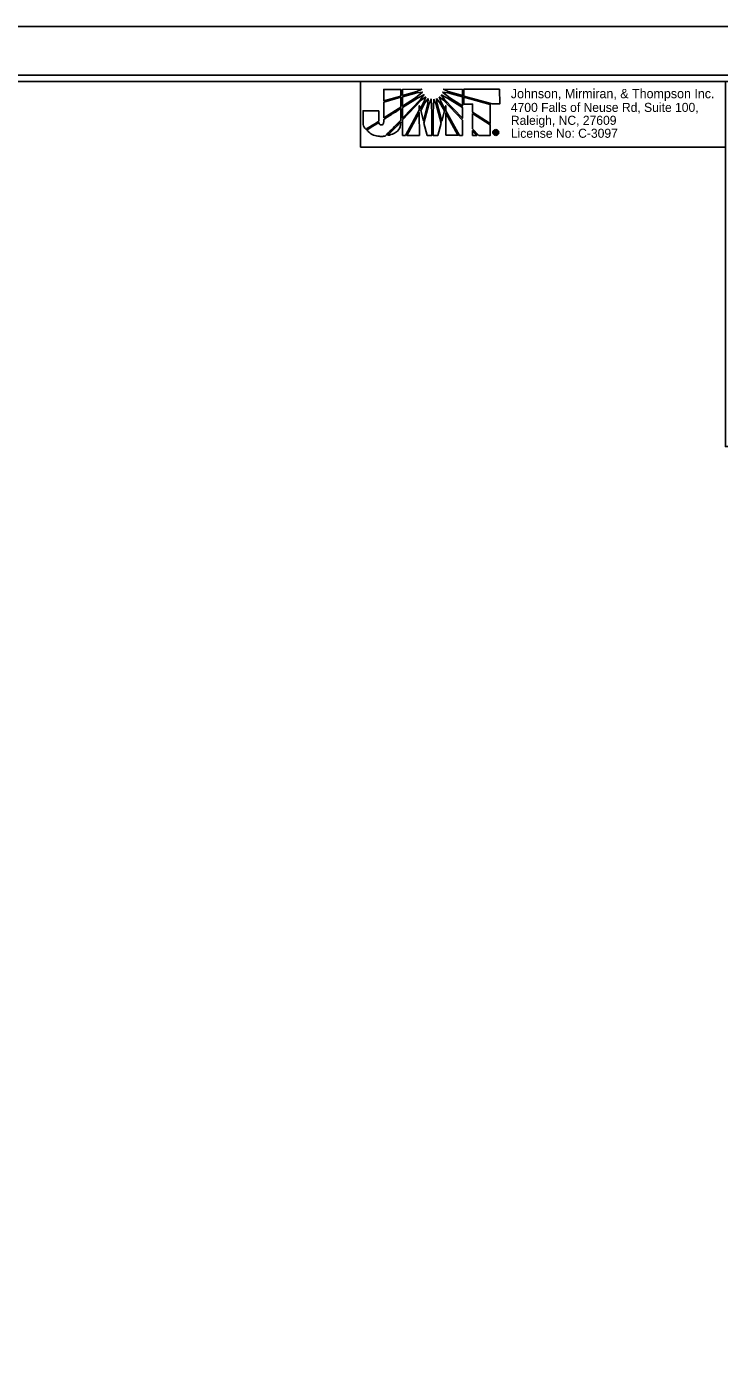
# Model space of a CAD drawing. Extents: x 2862872 to 2864765, y 971793 to 972888.
# Drawn here: x 2864051 to 2864336, y 972341 to 972888 of the extents above; entities that cross this region are included whole.
import ezdxf

# ---------------------------------------------------------------- set-up
doc = ezdxf.new("R2010")
doc.units = 0
for name, color, linetype in [('Prop Dimension Text', 7, 'Continuous'), ('Sheet Cutting Line CELL', 7, 'Continuous'), ('Sheet Plan CELL', 7, 'Continuous'), ('Sheet Plot Border Inside CELL', 7, 'Continuous'), ('Sheet Plot Border Outside CELL', 7, 'Continuous')]:
    doc.layers.add(name, color=color, linetype=linetype)

msp = doc.modelspace()

# ---------------------------------------------------------------- linework, layer by layer
at = {"layer": 'Prop Dimension Text'}
for p, q in [((2864205.18, 972862.53), (2864198.16, 972862.52)), ((2864198.16, 972862.52), (2864198.17, 972857.87)), ((2864198.17, 972857.87), (2864205.18, 972859.82)), ((2864205.18, 972859.31), (2864198.17, 972857.34)), ((2864205.18, 972859.82), (2864205.18, 972862.53)), ((2864205.18, 972855.25), (2864205.18, 972859.31)), ((2864213.8, 972862.57), (2864205.91, 972862.56)), ((2864205.91, 972862.56), (2864205.91, 972860.05)), ((2864205.91, 972860.05), (2864211.79, 972861.68)), ((2864211.79, 972861.13), (2864205.91, 972859.51)), ((2864205.91, 972859.51), (2864205.91, 972855.71)), ((2864205.91, 972855.71), (2864211.18, 972859.05)), ((2864211.99, 972858.97), (2864205.91, 972855.1)), ((2864205.92, 972850.72), (2864213.31, 972858.43)), ((2864211.18, 972859.05), (2864214.08, 972861.41)), ((2864211.79, 972861.68), (2864213.8, 972862.57)), ((2864214.08, 972861.41), (2864211.79, 972861.13)), ((2864214.66, 972860.33), (2864211.99, 972858.97)), ((2864213.31, 972858.43), (2864214.66, 972860.33)), ((2864215.47, 972859.48), (2864213.61, 972858.05)), ((2864214.62, 972857.24), (2864215.47, 972859.48)), ((2864216.48, 972858.86), (2864215.09, 972857.07)), ((2864216.28, 972856.69), (2864216.48, 972858.86)), ((2864217.64, 972858.55), (2864216.68, 972856.3)), ((2864217.94, 972853.01), (2864217.64, 972858.55)), ((2864218.79, 972858.55), (2864218.44, 972853.01)), ((2864219.72, 972856.3), (2864218.79, 972858.55)), ((2864219.92, 972858.86), (2864220.15, 972856.62)), ((2864221.27, 972857.08), (2864219.92, 972858.86)), ((2864220.91, 972859.49), (2864221.77, 972857.24)), ((2864222.78, 972858.05), (2864220.91, 972859.49)), ((2864221.73, 972860.33), (2864223.09, 972858.4)), ((2864224.44, 972858.98), (2864221.73, 972860.33)), ((2864222.35, 972861.42), (2864225.29, 972859.02)), ((2864224.51, 972861.15), (2864222.35, 972861.42)), ((2864230.52, 972862.55), (2864222.74, 972862.58)), ((2864222.74, 972862.58), (2864224.71, 972861.66)), ((2864223.09, 972858.4), (2864230.48, 972850.66)), ((2864230.48, 972855.16), (2864224.44, 972858.98)), ((2864230.52, 972859.5), (2864224.51, 972861.15)), ((2864224.71, 972861.66), (2864230.52, 972860.03)), ((2864225.29, 972859.02), (2864230.48, 972855.78)), ((2864230.48, 972855.78), (2864230.52, 972859.5)), ((2864230.52, 972860.03), (2864230.52, 972862.55)), ((2864245.81, 972862.6), (2864231.06, 972862.59)), ((2864231.06, 972862.59), (2864231.06, 972859.88)), ((2864231.06, 972859.88), (2864231.06, 972859.8)), ((2864231.06, 972859.8), (2864242.68, 972856.56)), ((2864231.07, 972859.38), (2864231.07, 972859.34)), ((2864241.94, 972856.29), (2864231.07, 972859.38)), ((2864231.07, 972859.34), (2864231.07, 972856.51)), ((2864245.82, 972856.56), (2864245.81, 972862.6)), ((2864198.17, 972857.34), (2864198.17, 972850.8)), ((2864198.17, 972850.8), (2864205.18, 972855.25)), ((2864205.91, 972855.1), (2864205.92, 972850.72)), ((2864213.61, 972858.05), (2864205.92, 972849.98)), ((2864207.08, 972843.61), (2864212.8, 972853.98)), ((2864212.8, 972852.97), (2864207.63, 972843.62)), ((2864212.8, 972853.98), (2864212.8, 972855.83)), ((2864212.8, 972855.83), (2864213.15, 972854.56)), ((2864212.86, 972843.62), (2864212.8, 972852.97)), ((2864213.15, 972854.56), (2864214.62, 972857.24)), ((2864215.09, 972857.07), (2864213.35, 972853.9)), ((2864213.35, 972853.9), (2864214.47, 972849.69)), ((2864214.47, 972849.69), (2864216.28, 972856.69)), ((2864216.68, 972856.3), (2864214.71, 972848.72)), ((2864217.95, 972843.66), (2864217.94, 972853.01)), ((2864218.44, 972853.01), (2864218.45, 972843.66)), ((2864221.74, 972848.61), (2864219.72, 972856.3)), ((2864220.15, 972856.62), (2864221.98, 972849.53)), ((2864223.09, 972853.79), (2864221.27, 972857.08)), ((2864221.77, 972857.24), (2864223.28, 972854.45)), ((2864221.98, 972849.53), (2864223.09, 972853.79)), ((2864230.48, 972849.93), (2864222.78, 972858.05)), ((2864223.28, 972854.45), (2864223.64, 972855.84)), ((2864223.64, 972855.84), (2864223.64, 972853.79)), ((2864223.64, 972853.79), (2864229.25, 972843.64)), ((2864228.67, 972843.67), (2864223.64, 972852.79)), ((2864223.64, 972852.79), (2864223.65, 972843.67)), ((2864230.48, 972850.66), (2864230.48, 972855.16)), ((2864231.07, 972856.51), (2864234.67, 972856.51)), ((2864234.67, 972856.51), (2864234.67, 972853.15)), ((2864234.67, 972853.15), (2864241.95, 972848.54)), ((2864241.95, 972848.54), (2864241.94, 972856.29)), ((2864242.68, 972856.56), (2864245.82, 972856.56)), ((2864205.92, 972849.98), (2864205.92, 972843.61)), ((2864214.71, 972848.72), (2864216.03, 972843.66)), ((2864220.4, 972843.66), (2864221.74, 972848.61)), ((2864230.49, 972843.64), (2864230.48, 972849.93)), ((2864234.67, 972852.57), (2864234.68, 972846.29)), ((2864241.95, 972848), (2864234.67, 972852.57)), ((2864241.95, 972843.65), (2864241.95, 972848)), ((2864205.92, 972843.61), (2864207.08, 972843.61)), ((2864207.63, 972843.62), (2864212.86, 972843.62)), ((2864216.03, 972843.66), (2864217.95, 972843.66)), ((2864218.45, 972843.66), (2864220.4, 972843.66)), ((2864223.65, 972843.67), (2864228.67, 972843.67)), ((2864229.25, 972843.64), (2864230.49, 972843.64)), ((2864234.68, 972846.29), (2864237.19, 972843.64)), ((2864236.5, 972843.64), (2864234.68, 972845.61)), ((2864234.68, 972845.61), (2864234.68, 972843.64)), ((2864234.68, 972843.64), (2864236.5, 972843.64)), ((2864237.19, 972843.64), (2864241.95, 972843.65)), ((2864243.8, 972844.31), (2864243.8, 972845.38)), ((2864243.8, 972845.38), (2864244.23, 972845.38)), ((2864244.04, 972844.31), (2864243.8, 972844.31)), ((2864244.23, 972845.18), (2864244.04, 972845.18)), ((2864244.04, 972845.18), (2864244.04, 972844.93)), ((2864244.04, 972844.93), (2864244.24, 972844.93)), ((2864244.24, 972844.73), (2864244.04, 972844.73)), ((2864244.04, 972844.73), (2864244.04, 972844.31)), ((2864244.23, 972846.02), (2864244.23, 972845.79)), ((2864244.23, 972845.79), (2864244.23, 972846.02)), ((2864244.23, 972845.38), (2864244.3, 972845.38)), ((2864244.23, 972845.38), (2864244.23, 972845.18)), ((2864244.23, 972845.18), (2864244.23, 972845.38)), ((2864244.26, 972845.18), (2864244.23, 972845.18)), ((2864244.24, 972844.93), (2864244.24, 972844.73)), ((2864244.24, 972844.73), (2864244.24, 972844.93)), ((2864244.24, 972844.93), (2864244.24, 972844.93)), ((2864244.25, 972844.73), (2864244.24, 972844.73)), ((2864244.24, 972843.89), (2864244.24, 972843.66)), ((2864244.24, 972843.66), (2864244.24, 972843.89)), ((2864244.24, 972843.89), (2864244.25, 972843.89)), ((2864244.25, 972843.66), (2864244.24, 972843.66))]:
    msp.add_line(p, q, dxfattribs=at)
msp.add_lwpolyline([(2864188.67, 972838.79), (2864338.58, 972838.79), (2864338.58, 972865.84), (2864188.67, 972865.84)], close=True, dxfattribs=at)
for points in [[(2864198.17, 972857.87), (2864205.18, 972859.82), (2864205.18, 972862.53), (2864198.16, 972862.52), (2864198.17, 972857.87)], [(2864198.17, 972850.8), (2864205.18, 972855.25), (2864205.18, 972859.31), (2864198.17, 972857.34), (2864198.17, 972850.8)], [(2864211.79, 972861.68), (2864213.8, 972862.57), (2864205.91, 972862.56), (2864205.91, 972860.05), (2864211.79, 972861.68)], [(2864205.91, 972859.51), (2864205.91, 972855.71), (2864211.18, 972859.05), (2864214.08, 972861.41), (2864211.79, 972861.13), (2864205.91, 972859.51)], [(2864205.91, 972855.1), (2864205.92, 972850.72), (2864213.31, 972858.43), (2864214.66, 972860.33), (2864211.99, 972858.97), (2864205.91, 972855.1)], [(2864215.47, 972859.48), (2864213.61, 972858.05), (2864205.92, 972849.98), (2864205.92, 972843.61), (2864207.08, 972843.61), (2864212.8, 972853.98), (2864212.8, 972855.83), (2864213.15, 972854.56), (2864214.62, 972857.24), (2864215.47, 972859.48)], [(2864216.48, 972858.86), (2864215.09, 972857.07), (2864213.35, 972853.9), (2864214.47, 972849.69), (2864216.28, 972856.69), (2864216.48, 972858.86)], [(2864216.68, 972856.3), (2864214.71, 972848.72), (2864216.03, 972843.66), (2864217.95, 972843.66), (2864217.94, 972853.01), (2864217.64, 972858.55), (2864216.68, 972856.3)], [(2864218.79, 972858.55), (2864218.44, 972853.01), (2864218.45, 972843.66), (2864220.4, 972843.66), (2864221.74, 972848.61), (2864219.72, 972856.3), (2864218.79, 972858.55)], [(2864219.92, 972858.86), (2864220.15, 972856.62), (2864221.98, 972849.53), (2864223.09, 972853.79), (2864221.27, 972857.08), (2864219.92, 972858.86)], [(2864220.91, 972859.49), (2864221.77, 972857.24), (2864223.28, 972854.45), (2864223.64, 972855.84), (2864223.64, 972853.79), (2864229.25, 972843.64), (2864230.49, 972843.64), (2864230.48, 972849.93), (2864222.78, 972858.05), (2864220.91, 972859.49)], [(2864221.73, 972860.33), (2864223.09, 972858.4), (2864230.48, 972850.66), (2864230.48, 972855.16), (2864224.44, 972858.98), (2864221.73, 972860.33)], [(2864222.35, 972861.42), (2864225.29, 972859.02), (2864230.48, 972855.78), (2864230.52, 972859.5), (2864224.51, 972861.15), (2864222.35, 972861.42)], [(2864224.71, 972861.66), (2864230.52, 972860.03), (2864230.52, 972862.55), (2864222.74, 972862.58), (2864224.71, 972861.66)], [(2864245.81, 972862.6), (2864231.06, 972862.59), (2864231.06, 972859.88), (2864231.06, 972859.8), (2864242.68, 972856.56), (2864245.82, 972856.56), (2864245.81, 972862.6)], [(2864231.07, 972859.38), (2864231.07, 972859.34), (2864231.07, 972856.51), (2864234.67, 972856.51), (2864234.67, 972853.15), (2864241.95, 972848.54), (2864241.94, 972856.29), (2864231.07, 972859.38)], [(2864207.63, 972843.62), (2864212.86, 972843.62), (2864212.8, 972852.97), (2864207.63, 972843.62)], [(2864223.65, 972843.67), (2864228.67, 972843.67), (2864223.64, 972852.79), (2864223.65, 972843.67)], [(2864234.67, 972852.57), (2864234.68, 972846.29), (2864237.19, 972843.64), (2864241.95, 972843.65), (2864241.95, 972848), (2864234.67, 972852.57), (2864234.67, 972852.57)], [(2864234.68, 972843.64), (2864234.68, 972843.64), (2864236.5, 972843.64), (2864234.68, 972845.61), (2864234.68, 972843.64)], [(2864244.7, 972844.57), (2864244.7, 972844.51), (2864244.71, 972844.47), (2864244.71, 972844.43), (2864244.74, 972844.31), (2864244.52, 972844.31)]]:
    msp.add_lwpolyline(points, dxfattribs=at)
for points, degree in [([(2864196.16, 972853.8), (2864196.16, 972853.8), (2864189.66, 972853.8), (2864189.66, 972853.8), (2864189.66, 972853.8), (2864189.67, 972849.73), (2864189.67, 972849.73), (2864189.67, 972849.73), (2864189.67, 972849.31), (2864189.67, 972849.31), (2864189.67, 972848.03), (2864190.08, 972847.03), (2864190.83, 972846.18), (2864190.83, 972846.18), (2864196.16, 972849.43), (2864196.16, 972849.51), (2864196.16, 972849.51), (2864196.16, 972853.8), (2864196.16, 972853.8)], 3), ([(2864197.17, 972847.96), (2864196.75, 972847.96), (2864196.39, 972848.19), (2864196.24, 972848.96), (2864196.24, 972848.96), (2864191.21, 972845.85), (2864191.21, 972845.85), (2864192.76, 972844.21), (2864195.24, 972843.24), (2864197.34, 972843.25), (2864197.88, 972843.25), (2864198.3, 972843.29), (2864198.87, 972843.41), (2864198.87, 972843.41), (2864205.19, 972849.95), (2864205.19, 972849.95), (2864205.19, 972849.95), (2864205.18, 972854.67), (2864205.18, 972854.67), (2864205.18, 972854.67), (2864198.17, 972850.2), (2864198.17, 972850.2), (2864198.18, 972848.43), (2864197.75, 972847.96), (2864197.17, 972847.96)], 3), ([(2864197.17, 972847.96), (2864196.75, 972847.96), (2864196.39, 972848.19), (2864196.24, 972848.96), (2864196.24, 972848.96), (2864191.21, 972845.85), (2864191.21, 972845.85), (2864192.76, 972844.21), (2864195.24, 972843.24), (2864197.34, 972843.25), (2864197.88, 972843.25), (2864198.3, 972843.29), (2864198.87, 972843.41), (2864198.87, 972843.41), (2864205.19, 972849.95), (2864205.19, 972849.95), (2864205.19, 972849.95), (2864205.18, 972854.67), (2864205.18, 972854.67), (2864205.18, 972854.67), (2864198.17, 972850.2), (2864198.17, 972850.2), (2864198.18, 972848.43), (2864197.75, 972847.96), (2864197.17, 972847.96)], 3), ([(2864205.19, 972849.2), (2864205.19, 972849.2), (2864199.73, 972843.56), (2864199.73, 972843.56), (2864202.4, 972844.22), (2864205.07, 972846), (2864205.19, 972849.2)], 3), ([(2864244.24, 972843.66), (2864243.91, 972843.66), (2864243.63, 972843.78), (2864243.4, 972844.01), (2864243.16, 972844.23), (2864243.05, 972844.52), (2864243.05, 972844.85), (2864243.05, 972845.18), (2864243.16, 972845.46), (2864243.4, 972845.68), (2864243.63, 972845.9), (2864243.9, 972846.02), (2864244.23, 972846.02)], 3), ([(2864244.23, 972845.79), (2864243.97, 972845.79), (2864243.75, 972845.71), (2864243.56, 972845.53), (2864243.38, 972845.35), (2864243.28, 972845.11), (2864243.28, 972844.85), (2864243.28, 972844.58), (2864243.38, 972844.35), (2864243.56, 972844.17), (2864243.75, 972843.98), (2864243.97, 972843.89), (2864244.24, 972843.89)], 3), ([(2864244.23, 972846.02), (2864244.57, 972846.02), (2864244.85, 972845.9), (2864245.08, 972845.68), (2864245.32, 972845.46), (2864245.43, 972845.18), (2864245.43, 972844.85)], 3), ([(2864244.25, 972843.89), (2864244.51, 972843.89), (2864244.73, 972843.98), (2864244.92, 972844.17), (2864245.1, 972844.35), (2864245.2, 972844.59), (2864245.2, 972844.85), (2864245.2, 972845.11), (2864245.1, 972845.35), (2864244.92, 972845.53), (2864244.73, 972845.71), (2864244.51, 972845.79), (2864244.23, 972845.79)], 3), ([(2864244.24, 972844.93), (2864244.4, 972844.93), (2864244.48, 972844.98), (2864244.48, 972845.06), (2864244.48, 972845.14), (2864244.41, 972845.18), (2864244.26, 972845.18)], 3), ([(2864245.43, 972844.85), (2864245.43, 972844.52), (2864245.32, 972844.24), (2864245.09, 972844), (2864244.86, 972843.78), (2864244.58, 972843.66), (2864244.25, 972843.66)], 3), ([(2864244.43, 972844.69), (2864244.4, 972844.71), (2864244.34, 972844.73), (2864244.25, 972844.73)], 2), ([(2864244.3, 972845.38), (2864244.58, 972845.39), (2864244.71, 972845.28), (2864244.71, 972845.06), (2864244.71, 972844.97), (2864244.67, 972844.89), (2864244.59, 972844.83)], 3), ([(2864244.52, 972844.31), (2864244.49, 972844.37), (2864244.47, 972844.43), (2864244.47, 972844.51), (2864244.47, 972844.61), (2864244.46, 972844.66), (2864244.43, 972844.69)], 3), ([(2864244.59, 972844.83), (2864244.65, 972844.79), (2864244.69, 972844.7), (2864244.7, 972844.57)], 2)]:
    msp.add_open_spline(points, degree=degree, dxfattribs=at)
at = {"layer": 'Sheet Cutting Line CELL'}
msp.add_line((2864555.63, 972888.32), (2862872.13, 972888.32), dxfattribs=at)
at = {"layer": 'Sheet Plan CELL'}
for points in [[(2863038.62, 971815.83), (2863038.6, 972865.8), (2864338.58, 972865.84), (2864338.6, 972715.78), (2864538.63, 972715.77), (2864538.63, 971815.83)], [(2863038.62, 971815.83), (2863038.6, 972865.8), (2864338.58, 972865.84), (2864338.6, 972715.78), (2864538.63, 972715.77), (2864538.63, 971815.83)], [(2864538.66, 972865.83), (2863038.62, 972865.83), (2863038.62, 971815.83), (2864538.63, 971815.83)], [(2864538.66, 972865.83), (2863038.62, 972865.83), (2863038.62, 971815.83), (2864538.63, 971815.83)]]:
    msp.add_lwpolyline(points, close=True, dxfattribs=at)
at = {"layer": 'Sheet Plot Border Inside CELL'}
msp.add_lwpolyline([(2862885.13, 971813.32), (2864551.12, 971813.33), (2864551.13, 972868.32), (2862885.13, 972868.32)], close=True, dxfattribs=at)
at = {"layer": 'Sheet Plot Border Outside CELL'}
msp.add_lwpolyline([(2862872.13, 971793.32), (2864555.63, 971793.32), (2864555.63, 972888.32), (2862872.13, 972888.32)], close=True, dxfattribs=at)
msp.add_lwpolyline([(2862872.13, 971793.32), (2864555.63, 971793.32), (2864555.63, 972888.32), (2862872.13, 972888.32)], close=True, dxfattribs=at)

# ---------------------------------------------------------------- texts
at = {"layer": 'Prop Dimension Text'}
for s, height, p in [('Johnson, Mirmiran, & Thompson Inc.', 3.8303, (2864250.41, 972858.91)), ('4700 Falls of Neuse Rd, Suite 100, ', 3.7209, (2864250.41, 972853.29)), ('Raleigh, NC, 27609', 3.7209, (2864250.41, 972847.98)), ('License No: C-3097', 3.7209, (2864250.41, 972842.66))]:
    msp.add_text(s, height=height, rotation=360, dxfattribs=at).set_placement(p)

doc.saveas('drawing.dxf')
